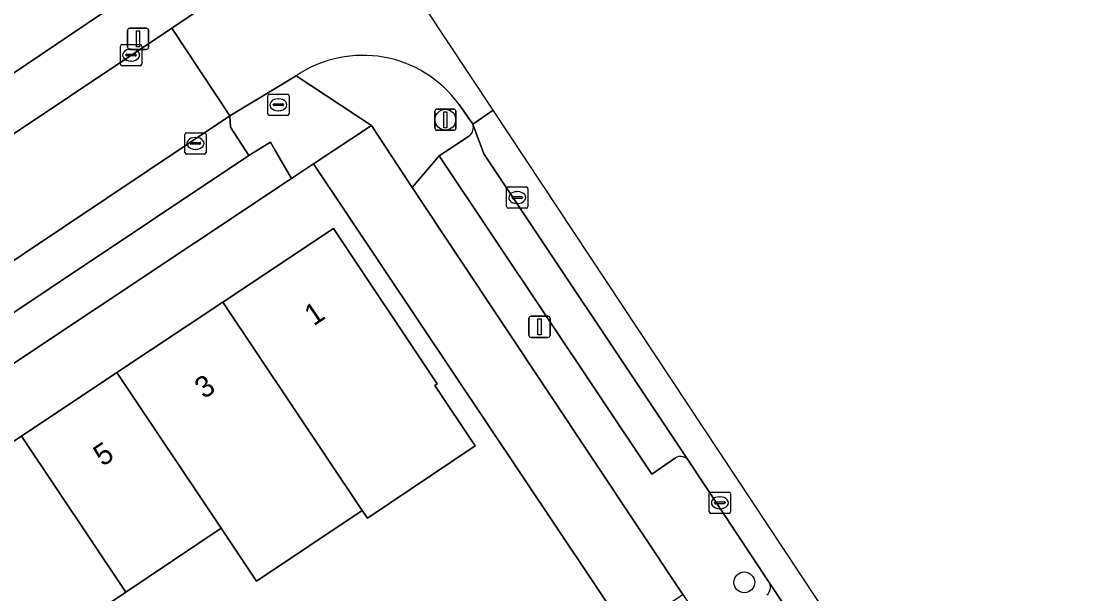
# Model space of a CAD drawing. Extents: x 158352 to 159489, y 383828 to 384603.
# Drawn here: x 158853 to 158903.3, y 384456.8 to 384483.7 of the extents above; entities that cross this region are included whole.
import ezdxf

# ---------------------------------------------------------------- set-up
doc = ezdxf.new("R2010")
doc.units = 0
for name, color, linetype in [('IMGEO_Boom', 7, 'Continuous'), ('IMGEO_Brandkraan', 7, 'Continuous'), ('IMGEO_Erf', 7, 'Continuous'), ('IMGEO_Groenvoorziening', 7, 'Continuous'), ('IMGEO_Kolk', 7, 'Continuous'), ('IMGEO_Lichtmast', 7, 'Continuous'), ('IMGEO_Pand', 7, 'Continuous'), ('IMGEO_Pand_nummerreeks', 7, 'Continuous'), ('IMGEO_Parkeervlak_open', 7, 'Continuous'), ('IMGEO_Rijbaan_lokaal_gesloten', 7, 'Continuous'), ('IMGEO_Rijbaan_lokaal_open', 7, 'Continuous'), ('IMGEO_Voetpad_open', 7, 'Continuous')]:
    doc.layers.add(name, color=color, linetype=linetype)

msp = doc.modelspace()

# ---------------------------------------------------------------- linework, layer by layer
at = {"layer": 'IMGEO_Boom'}
for centre in [(158873.008, 384479.082), (158887.081, 384457.306)]:
    msp.add_circle(centre, 0.489, dxfattribs=at)
at = {"layer": 'IMGEO_Brandkraan'}
for p, q in [((158864.721, 384480.286), (158865.573, 384480.286)), ((158864.646, 384479.36), (158864.646, 384480.212)), ((158864.905, 384479.78), (158864.905, 384479.792)), ((158864.948, 384479.829), (158865.346, 384479.829)), ((158865.134, 384480.066), (158865.159, 384480.066)), ((158865.389, 384479.792), (158865.389, 384479.78)), ((158865.647, 384480.212), (158865.647, 384479.36)), ((158865.573, 384479.286), (158864.721, 384479.286)), ((158865.343, 384479.743), (158864.945, 384479.743)), ((158865.157, 384479.506), (158865.132, 384479.506))]:
    msp.add_line(p, q, dxfattribs=at)
for points in [[(158864.721, 384480.286), (158865.573, 384480.286)], [(158864.646, 384479.36), (158864.646, 384480.212)], [(158865.647, 384480.212), (158865.647, 384479.36)], [(158865.573, 384479.286), (158864.721, 384479.286)]]:
    msp.add_lwpolyline(points, dxfattribs=at)
for centre, radius, start, end in [((158864.723, 384480.21), 0.0765, 91.552, 178.448), ((158864.723, 384480.21), 0.0765, 91.552, 178.448), ((158865.571, 384480.21), 0.0765, 1.552, 88.448), ((158865.571, 384480.21), 0.0765, 1.552, 88.448), ((158864.945, 384479.789), 0.0403, 85.8775, 175.7526), ((158864.942, 384479.779), 0.0366, 178.938, 274.7102), ((158865.346, 384479.786), 0.043, 264.8664, 352.4533), ((158865.35, 384479.791), 0.0386, 1.7309, 96.639), ((158864.723, 384479.362), 0.0765, 181.552, 268.448), ((158864.723, 384479.362), 0.0765, 181.552, 268.448), ((158865.571, 384479.362), 0.0765, 271.552, 358.448), ((158865.571, 384479.362), 0.0765, 271.552, 358.448)]:
    msp.add_arc(centre, radius, start, end, dxfattribs=at)
for centre, major_axis, ratio, start_param, end_param in [((158865.133, 384479.786), (-0.387, 0.002), 0.722429, 4.712389, 7.853982), ((158865.158, 384479.786), (-0.39, 0.002), 0.717154, 1.570796, 4.712389)]:
    msp.add_ellipse(centre, major_axis=major_axis, ratio=ratio, start_param=start_param, end_param=end_param, dxfattribs=at)
at = {"layer": 'IMGEO_Erf'}
msp.add_lwpolyline([(158871.439, 384475.884), (158869.53, 384478.817), (158866.797, 384476.999), (158881.542, 384454.976), (158884.184, 384456.734)], close=True, dxfattribs=at)
for points in [[(158881.542, 384454.976), (158866.797, 384476.999), (158865.767, 384476.314), (158824.454, 384448.838)], [(158848.053, 384460.87), (158853.047, 384464.192), (158857.548, 384467.185), (158862.533, 384470.501), (158867.746, 384473.968), (158872.617, 384466.647), (158872.513, 384466.577), (158874.416, 384463.732), (158869.334, 384460.333), (158869.095, 384460.69), (158864.119, 384457.362), (158862.455, 384459.85), (158857.962, 384456.845), (158852.977, 384453.51)]]:
    msp.add_lwpolyline(points, dxfattribs=at)
at = {"layer": 'IMGEO_Groenvoorziening'}
msp.add_lwpolyline([(158848.997, 384478.808), (158860.431, 384486.52), (158863.532, 384488.47), (158849.3, 384509.154)], dxfattribs=at)
at = {"layer": 'IMGEO_Kolk'}
for p, q in [((158857.712, 384481.698), (158857.712, 384482.55)), ((158857.787, 384482.624), (158858.639, 384482.624)), ((158858.2, 384482.404), (158858.225, 384482.404)), ((158858.713, 384482.55), (158858.713, 384481.698)), ((158857.971, 384482.118), (158857.971, 384482.13)), ((158858.409, 384482.081), (158858.011, 384482.081)), ((158858.014, 384482.167), (158858.412, 384482.167)), ((158858.223, 384481.844), (158858.198, 384481.844)), ((158858.455, 384482.13), (158858.455, 384482.118)), ((158858.639, 384481.624), (158857.787, 384481.624)), ((158860.743, 384477.54), (158860.743, 384478.392)), ((158860.818, 384478.466), (158861.67, 384478.466)), ((158861.231, 384478.246), (158861.256, 384478.246)), ((158861.744, 384478.392), (158861.744, 384477.54)), ((158861.002, 384477.96), (158861.002, 384477.972)), ((158861.44, 384477.923), (158861.042, 384477.923)), ((158861.045, 384478.009), (158861.443, 384478.009)), ((158861.486, 384477.972), (158861.486, 384477.96)), ((158861.67, 384477.466), (158860.818, 384477.466)), ((158861.254, 384477.686), (158861.229, 384477.686)), ((158875.89, 384474.991), (158875.89, 384475.843)), ((158875.965, 384475.917), (158876.817, 384475.917)), ((158876.891, 384475.843), (158876.891, 384474.991)), ((158876.149, 384475.411), (158876.149, 384475.423)), ((158876.587, 384475.374), (158876.189, 384475.374)), ((158876.192, 384475.46), (158876.59, 384475.46)), ((158876.378, 384475.697), (158876.403, 384475.697)), ((158876.633, 384475.423), (158876.633, 384475.411)), ((158876.817, 384474.917), (158875.965, 384474.917)), ((158876.401, 384475.137), (158876.376, 384475.137)), ((158885.429, 384460.625), (158885.429, 384461.477)), ((158885.504, 384461.551), (158886.356, 384461.551)), ((158885.917, 384461.331), (158885.942, 384461.331)), ((158886.43, 384461.477), (158886.43, 384460.625)), ((158885.688, 384461.045), (158885.688, 384461.057)), ((158886.126, 384461.008), (158885.728, 384461.008)), ((158885.731, 384461.094), (158886.129, 384461.094)), ((158885.94, 384460.771), (158885.915, 384460.771)), ((158886.172, 384461.057), (158886.172, 384461.045)), ((158886.356, 384460.551), (158885.504, 384460.551))]:
    msp.add_line(p, q, dxfattribs=at)
for points in [[(158857.712, 384481.698), (158857.712, 384482.55)], [(158857.787, 384482.624), (158858.639, 384482.624)], [(158858.713, 384482.55), (158858.713, 384481.698)], [(158858.639, 384481.624), (158857.787, 384481.624)], [(158860.743, 384477.54), (158860.743, 384478.392)], [(158860.818, 384478.466), (158861.67, 384478.466)], [(158861.744, 384478.392), (158861.744, 384477.54)], [(158861.67, 384477.466), (158860.818, 384477.466)], [(158875.89, 384474.991), (158875.89, 384475.843)], [(158875.965, 384475.917), (158876.817, 384475.917)], [(158876.891, 384475.843), (158876.891, 384474.991)], [(158876.817, 384474.917), (158875.965, 384474.917)], [(158885.429, 384460.625), (158885.429, 384461.477)], [(158885.504, 384461.551), (158886.356, 384461.551)], [(158886.43, 384461.477), (158886.43, 384460.625)], [(158886.356, 384460.551), (158885.504, 384460.551)]]:
    msp.add_lwpolyline(points, dxfattribs=at)
for centre, radius, start, end in [((158857.789, 384482.548), 0.0765, 91.552, 178.448), ((158857.789, 384482.548), 0.0765, 91.552, 178.448), ((158858.637, 384482.548), 0.0765, 1.552, 88.448), ((158858.637, 384482.548), 0.0765, 1.552, 88.448), ((158858.011, 384482.127), 0.0403, 85.8775, 175.7526), ((158858.008, 384482.117), 0.0366, 178.938, 274.7102), ((158858.412, 384482.124), 0.043, 264.8664, 352.4533), ((158858.416, 384482.129), 0.0386, 1.7309, 96.639), ((158857.789, 384481.7), 0.0765, 181.552, 268.448), ((158857.789, 384481.7), 0.0765, 181.552, 268.448), ((158858.637, 384481.7), 0.0765, 271.552, 358.448), ((158858.637, 384481.7), 0.0765, 271.552, 358.448), ((158860.82, 384478.39), 0.0765, 91.552, 178.448), ((158860.82, 384478.39), 0.0765, 91.552, 178.448), ((158861.668, 384478.39), 0.0765, 1.552, 88.448), ((158861.668, 384478.39), 0.0765, 1.552, 88.448), ((158861.042, 384477.969), 0.0403, 85.8775, 175.7526), ((158861.039, 384477.959), 0.0366, 178.938, 274.7102), ((158861.443, 384477.966), 0.043, 264.8664, 352.4533), ((158861.447, 384477.971), 0.0386, 1.7309, 96.639), ((158860.82, 384477.542), 0.0765, 181.552, 268.448), ((158860.82, 384477.542), 0.0765, 181.552, 268.448), ((158861.668, 384477.542), 0.0765, 271.552, 358.448), ((158861.668, 384477.542), 0.0765, 271.552, 358.448), ((158875.967, 384475.841), 0.0765, 91.552, 178.448), ((158875.967, 384475.841), 0.0765, 91.552, 178.448), ((158876.815, 384475.841), 0.0765, 1.552, 88.448), ((158876.815, 384475.841), 0.0765, 1.552, 88.448), ((158876.189, 384475.42), 0.0403, 85.8775, 175.7526), ((158876.186, 384475.41), 0.0366, 178.938, 274.7102), ((158876.59, 384475.417), 0.043, 264.8664, 352.4533), ((158876.594, 384475.422), 0.0386, 1.7309, 96.639), ((158875.967, 384474.993), 0.0765, 181.552, 268.448), ((158875.967, 384474.993), 0.0765, 181.552, 268.448), ((158876.815, 384474.993), 0.0765, 271.552, 358.448), ((158876.815, 384474.993), 0.0765, 271.552, 358.448), ((158885.506, 384461.475), 0.0765, 91.552, 178.448), ((158885.506, 384461.475), 0.0765, 91.552, 178.448), ((158886.354, 384461.475), 0.0765, 1.552, 88.448), ((158886.354, 384461.475), 0.0765, 1.552, 88.448), ((158885.728, 384461.054), 0.0403, 85.8775, 175.7526), ((158885.725, 384461.044), 0.0366, 178.938, 274.7102), ((158886.129, 384461.051), 0.043, 264.8664, 352.4533), ((158886.133, 384461.056), 0.0386, 1.7309, 96.639), ((158885.506, 384460.627), 0.0765, 181.552, 268.448), ((158885.506, 384460.627), 0.0765, 181.552, 268.448), ((158886.354, 384460.627), 0.0765, 271.552, 358.448), ((158886.354, 384460.627), 0.0765, 271.552, 358.448)]:
    msp.add_arc(centre, radius, start, end, dxfattribs=at)
for centre, major_axis, ratio, start_param, end_param in [((158858.199, 384482.124), (-0.387, 0.002), 0.722429, 4.712389, 7.853982), ((158858.224, 384482.124), (-0.39, 0.002), 0.717154, 1.570796, 4.712389), ((158861.23, 384477.966), (-0.387, 0.002), 0.722429, 4.712389, 7.853982), ((158861.255, 384477.966), (-0.39, 0.002), 0.717154, 1.570796, 4.712389), ((158876.377, 384475.417), (-0.387, 0.002), 0.722429, 4.712389, 7.853982), ((158876.402, 384475.417), (-0.39, 0.002), 0.717154, 1.570796, 4.712389), ((158885.916, 384461.051), (-0.387, 0.002), 0.722429, 4.712389, 7.853982), ((158885.941, 384461.051), (-0.39, 0.002), 0.717154, 1.570796, 4.712389)]:
    msp.add_ellipse(centre, major_axis=major_axis, ratio=ratio, start_param=start_param, end_param=end_param, dxfattribs=at)
at = {"layer": 'IMGEO_Lichtmast'}
for p, q in [((158858.044, 384482.49), (158858.044, 384483.29)), ((158858.044, 384483.29), (158858.044, 384482.49)), ((158858.144, 384483.39), (158858.934, 384483.39)), ((158858.934, 384483.39), (158858.144, 384483.39)), ((158859.034, 384483.29), (158859.034, 384482.49)), ((158859.034, 384482.49), (158859.034, 384483.29)), ((158858.934, 384482.39), (158858.144, 384482.39)), ((158858.144, 384482.39), (158858.934, 384482.39)), ((158872.513, 384478.682), (158872.513, 384479.482)), ((158872.513, 384479.482), (158872.513, 384478.682)), ((158872.613, 384479.582), (158873.403, 384479.582)), ((158873.403, 384479.582), (158872.613, 384479.582)), ((158873.503, 384479.482), (158873.503, 384478.682)), ((158873.503, 384478.682), (158873.503, 384479.482)), ((158873.403, 384478.582), (158872.613, 384478.582)), ((158872.613, 384478.582), (158873.403, 384478.582)), ((158876.944, 384468.935), (158876.944, 384469.735)), ((158876.944, 384469.735), (158876.944, 384468.935)), ((158877.044, 384469.835), (158877.834, 384469.835)), ((158877.834, 384469.835), (158877.044, 384469.835)), ((158877.934, 384469.735), (158877.934, 384468.935)), ((158877.934, 384468.935), (158877.934, 384469.735)), ((158877.834, 384468.835), (158877.044, 384468.835)), ((158877.044, 384468.835), (158877.834, 384468.835))]:
    msp.add_line(p, q, dxfattribs=at)
for points in [[(158858.464, 384483.265), (158858.614, 384483.265), (158858.614, 384482.515), (158858.464, 384482.515), (158858.464, 384483.265)], [(158872.933, 384479.457), (158873.083, 384479.457), (158873.083, 384478.707), (158872.933, 384478.707), (158872.933, 384479.457)], [(158877.364, 384469.71), (158877.514, 384469.71), (158877.514, 384468.96), (158877.364, 384468.96), (158877.364, 384469.71)]]:
    msp.add_lwpolyline(points, dxfattribs=at)
for centre, start, end in [((158858.144, 384483.29), 90, 180), ((158858.144, 384483.29), 90, 180), ((158858.934, 384483.29), 0, 90), ((158858.934, 384483.29), 360, 90), ((158858.144, 384482.49), 180, 270), ((158858.144, 384482.49), 180, 270), ((158858.934, 384482.49), 270, 0), ((158858.934, 384482.49), 270, 0), ((158872.613, 384479.482), 90, 180), ((158872.613, 384479.482), 90, 180), ((158873.403, 384479.482), 0, 90), ((158873.403, 384479.482), 360, 90), ((158872.613, 384478.682), 180, 270), ((158872.613, 384478.682), 180, 270), ((158873.403, 384478.682), 270, 0), ((158873.403, 384478.682), 270, 0), ((158877.044, 384469.735), 90, 180), ((158877.044, 384469.735), 90, 180), ((158877.834, 384469.735), 0, 90), ((158877.834, 384469.735), 360, 90), ((158877.044, 384468.935), 180, 270), ((158877.044, 384468.935), 180, 270), ((158877.834, 384468.935), 270, 0), ((158877.834, 384468.935), 270, 0)]:
    msp.add_arc(centre, 0.1, start, end, dxfattribs=at)
at = {"layer": 'IMGEO_Pand'}
for points in [[(158867.746, 384473.968), (158862.533, 384470.501), (158869.095, 384460.69), (158869.334, 384460.333), (158874.416, 384463.732), (158872.513, 384466.577), (158872.617, 384466.647)], [(158862.533, 384470.501), (158857.548, 384467.185), (158862.455, 384459.85), (158864.119, 384457.362), (158869.095, 384460.69)], [(158862.455, 384459.85), (158857.548, 384467.185), (158853.047, 384464.192), (158857.962, 384456.845)], [(158853.047, 384464.192), (158848.053, 384460.87), (158852.977, 384453.51), (158857.962, 384456.845)]]:
    msp.add_lwpolyline(points, close=True, dxfattribs=at)
at = {"layer": 'IMGEO_Parkeervlak_open'}
for points in [[(158820.811, 384450.589), (158821.645, 384449.296), (158863.755, 384477.4), (158862.897, 384478.725), (158862.853, 384479.261), (158820.226, 384450.737)], [(158884.4, 384463.1), (158874.82, 384477.468), (158874.302, 384478.867)], [(158874.137, 384478.318), (158872.711, 384477.381), (158882.723, 384462.395), (158883.84, 384463.169)], [(158898.259, 384442.243), (158888.28, 384457.252)]]:
    msp.add_lwpolyline(points, dxfattribs=at)
for centre, radius, start, end in [((158873.833, 384478.709), 0.495, 307.8904, 18.6537), ((158884.075, 384462.772), 0.462, 45.2993, 120.6522), ((158887.878, 384457.075), 0.439, 306.5806, 23.8259)]:
    msp.add_arc(centre, radius, start, end, dxfattribs=at)
at = {"layer": 'IMGEO_Rijbaan_lokaal_gesloten'}
for points in [[(158875.263, 384479.53), (158874.302, 384478.867), (158874.82, 384477.468), (158884.4, 384463.1), (158888.28, 384457.252), (158898.259, 384442.243), (158899.028, 384441.124), (158902.775, 384435.489), (158906.139, 384430.429), (158906.908, 384429.304), (158920.007, 384409.58), (158920.763, 384408.459), (158933.684, 384389.073), (158934.462, 384387.903), (158948.108, 384367.417), (158948.862, 384366.323), (158955.957, 384355.688), (158956.746, 384354.542), (158963.568, 384344.252), (158966.627, 384339.706), (158967.515, 384338.34), (158974.141, 384328.364)], [(158974.618, 384328.235), (158976.716, 384325.103), (158977.265, 384325.504), (158977.265, 384325.504), (158875.263, 384479.53)]]:
    msp.add_lwpolyline(points, dxfattribs=at)
at = {"layer": 'IMGEO_Rijbaan_lokaal_open'}
for points in [[(158873.653, 384479.797), (158874.302, 384478.867), (158875.263, 384479.53), (158869.943, 384487.563), (158865.509, 384494.258)], [(158863.954, 384485.975), (158860.122, 384483.398), (158862.853, 384479.261), (158865.985, 384481.149)]]:
    msp.add_lwpolyline(points, dxfattribs=at)
msp.add_lwpolyline([(158817.271, 384454.789), (158820.001, 384450.597), (158820.226, 384450.737), (158862.853, 384479.261), (158860.122, 384483.398)], close=True, dxfattribs=at)
msp.add_arc((158869.121, 384476.514), 5.597, 35.9229, 124.0782, dxfattribs=at)
at = {"layer": 'IMGEO_Voetpad_open'}
for points in [[(158744.541, 384406.289), (158761.522, 384417.613), (158799.316, 384442.816), (158817.271, 384454.789), (158860.122, 384483.398), (158863.954, 384485.975), (158863.532, 384488.47), (158860.431, 384486.52), (158848.997, 384478.808), (158826.388, 384463.558), (158801.455, 384446.936), (158759.672, 384418.896), (158756.032, 384416.448), (158743.282, 384407.89)], [(158865.985, 384481.149), (158869.53, 384478.817), (158871.439, 384475.884), (158872.711, 384477.381), (158874.137, 384478.318)], [(158874.302, 384478.867), (158873.653, 384479.797)], [(158815.486, 384442.875), (158818.522, 384444.893), (158820.38, 384446.128), (158824.454, 384448.838), (158865.767, 384476.314), (158864.982, 384477.657), (158864.771, 384478.02), (158863.755, 384477.4), (158821.645, 384449.296), (158820.811, 384450.589)], [(158883.84, 384463.169), (158882.723, 384462.395), (158872.711, 384477.381), (158871.439, 384475.884), (158884.184, 384456.734), (158885.345, 384454.99), (158899.598, 384433.573), (158960.345, 384342.297), (158973.377, 384322.58), (158974.997, 384323.628), (158974.847, 384323.853), (158976.716, 384325.103), (158974.618, 384328.235)], [(158888.28, 384457.252), (158884.4, 384463.1)]]:
    msp.add_lwpolyline(points, dxfattribs=at)
msp.add_lwpolyline([(158869.53, 384478.817), (158865.985, 384481.149), (158862.853, 384479.261), (158862.897, 384478.725), (158863.755, 384477.4), (158864.771, 384478.02), (158864.982, 384477.657), (158865.767, 384476.314), (158866.797, 384476.999)], close=True, dxfattribs=at)
for centre, radius, start, end in [((158869.121, 384476.514), 5.597, 35.9229, 124.0782), ((158873.833, 384478.709), 0.495, 307.8904, 18.6537), ((158884.075, 384462.772), 0.462, 45.2993, 120.6522), ((158887.878, 384457.075), 0.439, 306.5806, 23.8259)]:
    msp.add_arc(centre, radius, start, end, dxfattribs=at)

# ---------------------------------------------------------------- texts
at = {"layer": 'IMGEO_Pand_nummerreeks'}
for s, rotation, p in [('1', 34.1311, (158866.805, 384469.345)), ('3', 34.0452, (158861.643, 384465.91)), ('5', 33.7601, (158856.871, 384462.735))]:
    msp.add_text(s, height=1, rotation=rotation, dxfattribs=at).set_placement(p)

doc.saveas('drawing.dxf')
